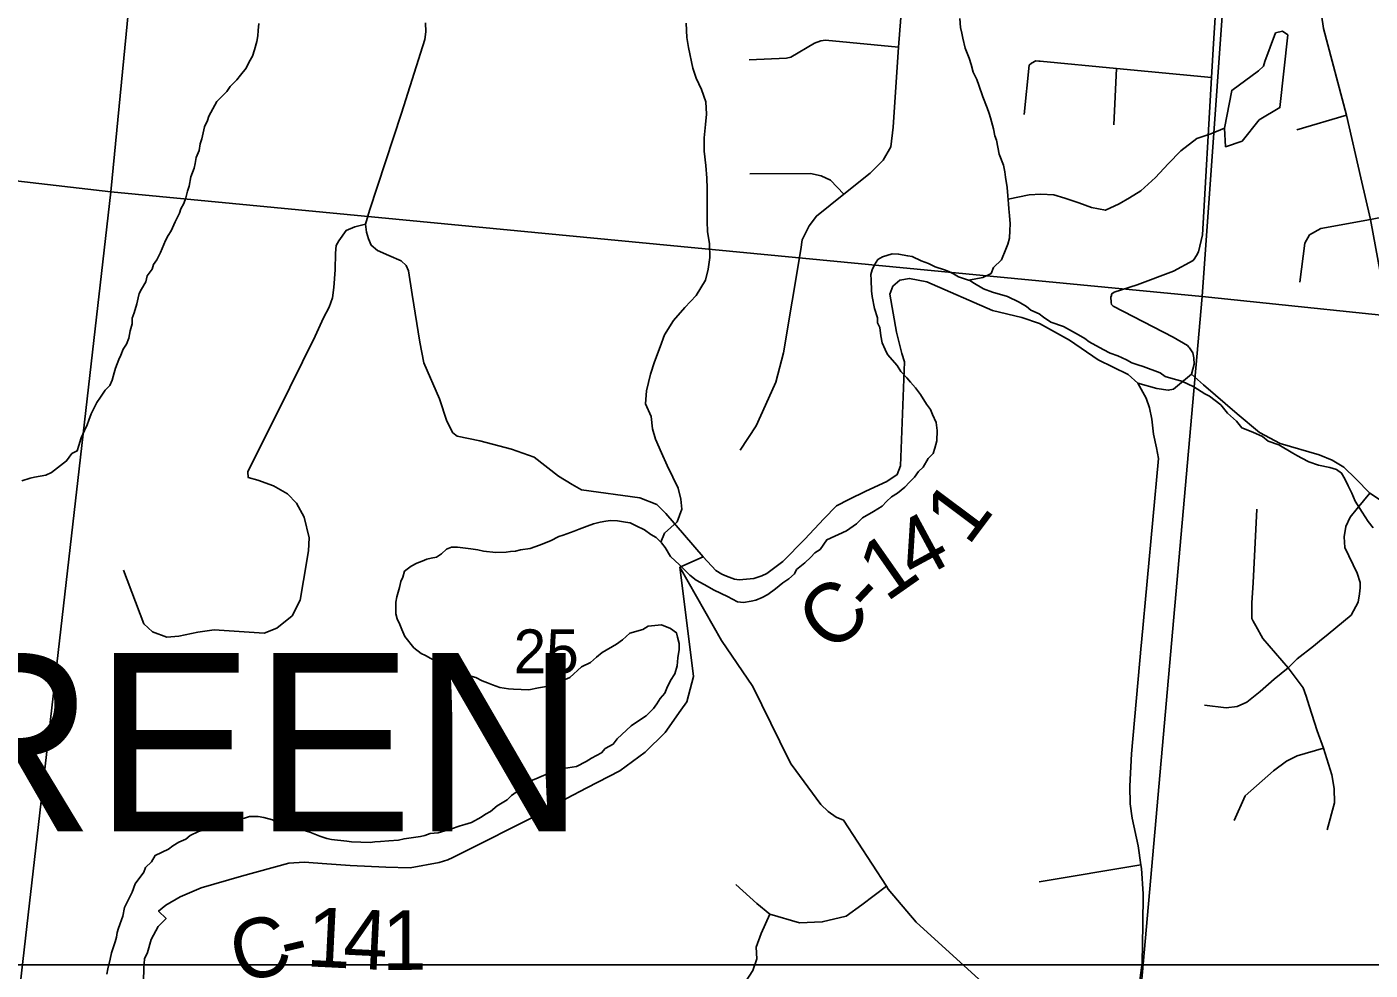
# Model space of a CAD drawing. Extents: x 0 to 34, y 0 to 22.
# Drawn here: x 4.767 to 6.05, y 17.836 to 18.737 of the extents above; entities that cross this region are included whole.
import ezdxf

# ---------------------------------------------------------------- set-up
doc = ezdxf.new("R2010")
doc.units = 0
for name, color, linetype in [('GM_X_Corporation', 7, 'Continuous'), ('GM_X_County_Road', 7, 'Continuous'), ('GM_X_County_Road_Text', 7, 'Continuous'), ('GM_X_Minor_Lake', 7, 'Continuous'), ('GM_X_Minor_River', 7, 'Continuous'), ('GM_X_Section_Text', 7, 'Continuous'), ('GM_X_Township_Road', 7, 'Continuous'), ('GM_X_Township_Text', 7, 'Continuous'), ('SH_Masking', 7, 'Continuous'), ('SH_Text', 7, 'Continuous')]:
    doc.layers.add(name, color=color, linetype=linetype)

msp = doc.modelspace()

# ---------------------------------------------------------------- linework, layer by layer
at = {"layer": 'GM_X_Corporation'}
for points in [[(3.9403, 19.7031), (4.9462, 19.5973), (4.8473, 18.5791), (3.8378, 18.696)], [(5.9616, 19.4927), (5.8893, 18.4792), (4.8473, 18.5791), (4.9462, 19.5973)], [(5.9616, 19.4927), (6.9413, 19.3834), (6.8431, 18.3799), (5.8893, 18.4792)], [(4.8473, 18.5791), (4.7377, 17.6243), (3.7435, 17.7155), (3.8378, 18.696)], [(4.8473, 18.5791), (5.8893, 18.4792), (5.7989, 17.4561), (4.7377, 17.6243)], [(6.8431, 18.3799), (6.7271, 17.3517), (5.7989, 17.4561), (5.8893, 18.4792)]]:
    msp.add_lwpolyline(points, close=True, dxfattribs=at)
at = {"layer": 'GM_X_County_Road'}
for p, q in [((5.3905, 18.2207), (5.4127, 18.2304)), ((5.3952, 18.1827), (5.3905, 18.2207))]:
    msp.add_line(p, q, dxfattribs=at)
for points in [[(5.8839, 18.5182), (5.8859, 18.5217), (5.8895, 18.5379), (5.8981, 18.6884), (5.9, 18.7207), (5.912, 18.9053), (5.9168, 18.9788)], [(5.4127, 18.2304), (5.3773, 18.2718), (5.3685, 18.2804), (5.3524, 18.287), (5.2965, 18.2945), (5.2876, 18.2997), (5.2746, 18.3077), (5.2513, 18.3256), (5.2299, 18.3335), (5.1995, 18.3413), (5.178, 18.3458), (5.1739, 18.349), (5.1682, 18.3602), (5.161, 18.3815), (5.1461, 18.4159), (5.1422, 18.4354), (5.1351, 18.481), (5.1316, 18.5038), (5.1292, 18.5088), (5.1246, 18.5132), (5.1128, 18.5184), (5.1017, 18.5232), (5.0957, 18.5281), (5.0934, 18.5341), (5.0914, 18.5407), (5.0903, 18.5483), (5.0941, 18.5614), (5.1249, 18.6542), (5.1472, 18.7247), (5.148, 18.7319), (5.1476, 18.7405)], [(5.8029, 18.4808), (5.8032, 18.4818), (5.8054, 18.4833), (5.8273, 18.4902), (5.8618, 18.5035), (5.8807, 18.5135), (5.8824, 18.5156), (5.8834, 18.5173), (5.8839, 18.5182)], [(5.4127, 18.2304), (5.4249, 18.2176), (5.4307, 18.2141), (5.435, 18.2121), (5.4428, 18.2092), (5.4473, 18.2086), (5.4613, 18.2098), (5.4688, 18.2124), (5.4736, 18.2147), (5.4888, 18.226), (5.5099, 18.2474), (5.528, 18.2669), (5.5402, 18.2791), (5.5518, 18.2852), (5.5683, 18.2934), (5.5883, 18.3026), (5.598, 18.3091), (5.6013, 18.3174), (5.605, 18.4168), (5.6026, 18.4248), (5.5975, 18.4451), (5.5912, 18.4814), (5.5941, 18.4889), (5.6007, 18.4948), (5.6098, 18.4964), (5.6264, 18.4932), (5.6892, 18.4657), (5.7171, 18.4591), (5.7339, 18.4533), (5.7626, 18.4375), (5.79, 18.4188), (5.8188, 18.4046), (5.828, 18.3963)], [(5.879, 18.4051), (5.8817, 18.4145), (5.8815, 18.4207), (5.8803, 18.4255), (5.8772, 18.43), (5.8767, 18.4307), (5.8752, 18.4323), (5.8616, 18.4404), (5.8042, 18.47), (5.8026, 18.4716), (5.8024, 18.4735), (5.8022, 18.4788), (5.8026, 18.4798), (5.8029, 18.4808)], [(5.828, 18.3963), (5.846, 18.3912), (5.857, 18.3897), (5.862, 18.3907), (5.879, 18.4051)], [(5.8315, 18.1487), (5.8476, 18.3243), (5.8457, 18.3346), (5.8427, 18.3476), (5.8413, 18.3621), (5.839, 18.3728), (5.8359, 18.382), (5.828, 18.3963)], [(5.879, 18.4051), (5.8905, 18.3947), (5.9226, 18.3671), (5.9442, 18.3494), (5.9637, 18.3388), (6.0009, 18.328), (6.0136, 18.3228), (6.0245, 18.3163), (6.036, 18.305), (6.0493, 18.2915), (6.0768, 18.2732), (6.0947, 18.2643), (6.1384, 18.2479), (6.1507, 18.2449), (6.1624, 18.2455), (6.1754, 18.2495), (6.1913, 18.2616), (6.2051, 18.2755), (6.2269, 18.3064), (6.2439, 18.3224), (6.2453, 18.3236), (6.2495, 18.3272)], [(5.4947, 18.0367), (5.4604, 18.1066), (5.4302, 18.1506), (5.3905, 18.2207)], [(5.3018, 18.0099), (5.3332, 18.0261), (5.3573, 18.0441), (5.3765, 18.0627), (5.3914, 18.084), (5.3971, 18.092), (5.4035, 18.1163), (5.3952, 18.1827)], [(5.7951, 17.4608), (5.8068, 17.5857), (5.8243, 17.786), (5.8319, 17.8427), (5.8327, 17.8792), (5.8329, 17.9088), (5.8314, 17.9328), (5.8309, 17.9365), (5.8283, 17.9545), (5.8224, 17.9809), (5.8205, 17.9946), (5.8203, 18.0114), (5.8217, 18.0425), (5.8312, 18.1458), (5.8315, 18.1487)], [(5.8243, 17.786), (5.734, 17.7824), (5.7265, 17.7846), (5.7175, 17.7898), (5.6762, 17.8273), (5.6163, 17.8816), (5.5896, 17.9132), (5.5878, 17.916), (5.5467, 17.9791), (5.5399, 17.982), (5.5322, 17.9872), (5.5252, 17.9939), (5.4969, 18.0324), (5.4947, 18.0367)], [(4.8763, 17.7392), (4.8786, 17.8378), (4.8794, 17.8465), (4.8821, 17.8527), (4.8858, 17.865), (4.8925, 17.8774), (4.8999, 17.8853), (4.8928, 17.8923), (4.8996, 17.8978), (4.9135, 17.9059), (4.9334, 17.9145), (4.9719, 17.9255), (5.0173, 17.9381), (5.0318, 17.9389), (5.0534, 17.9373), (5.0757, 17.9357), (5.1098, 17.9342), (5.1329, 17.9337), (5.1607, 17.9388), (5.1691, 17.9413), (5.1737, 17.9434), (5.2614, 17.9874), (5.2823, 17.9999), (5.3018, 18.0099)]]:
    msp.add_lwpolyline(points, dxfattribs=at)
at = {"layer": 'GM_X_Minor_Lake'}
for points in [[(5.9274, 18.6275), (5.9439, 18.648), (5.9636, 18.6596), (5.9711, 18.729), (5.9659, 18.7325), (5.9594, 18.7308), (5.9492, 18.7037), (5.9479, 18.6992), (5.9432, 18.6947), (5.9176, 18.676), (5.9106, 18.64)], [(5.9106, 18.64), (5.9117, 18.6222), (5.9274, 18.6275)]]:
    msp.add_lwpolyline(points, dxfattribs=at)
at = {"layer": 'GM_X_Minor_River'}
for points in [[(5.3725, 18.2447), (5.376, 18.253), (5.3881, 18.264), (5.3923, 18.2761), (5.3914, 18.2856), (5.389, 18.296), (5.384, 18.3067), (5.3783, 18.3179), (5.3729, 18.3299), (5.3672, 18.343), (5.3645, 18.3529), (5.3633, 18.3644), (5.3579, 18.3767), (5.3587, 18.3892), (5.3626, 18.4051), (5.3663, 18.4168), (5.3717, 18.431), (5.3758, 18.4427), (5.3846, 18.4562), (5.3952, 18.4688), (5.4061, 18.4802), (5.4149, 18.4948), (5.4175, 18.5054), (5.4193, 18.5164), (5.419, 18.5297), (5.417, 18.5408), (5.4165, 18.551), (5.4168, 18.5605), (5.4168, 18.572), (5.4167, 18.5822), (5.4162, 18.5921), (5.4154, 18.6043), (5.4139, 18.618), (5.4139, 18.6306), (5.415, 18.6435), (5.4161, 18.6533), (5.4153, 18.6651), (5.4111, 18.6767), (5.4061, 18.6875), (5.4029, 18.6971), (5.3989, 18.7169), (5.3973, 18.7265), (5.3966, 18.7402)], [(5.6667, 18.7067), (5.6629, 18.7163), (5.6609, 18.7259), (5.6599, 18.7305), (5.6586, 18.7359), (5.6578, 18.7447)], [(4.9765, 18.6972), (4.9794, 18.7031), (4.9826, 18.7087), (4.9843, 18.7148), (4.9865, 18.7227), (4.9875, 18.728), (4.988, 18.7333), (4.9886, 18.7397)], [(5.4586, 18.1882), (5.4632, 18.1892), (5.4693, 18.1917), (5.4747, 18.1945), (5.4818, 18.2), (5.4888, 18.2058), (5.4946, 18.2094), (5.5001, 18.2142), (5.5021, 18.2183), (5.51, 18.2248), (5.5158, 18.2303), (5.5194, 18.2344), (5.5244, 18.2376), (5.5308, 18.2469), (5.5497, 18.2554), (5.5591, 18.2619), (5.565, 18.2678), (5.5754, 18.2739), (5.5836, 18.2789), (5.5879, 18.2833), (5.5926, 18.2877), (5.5984, 18.2913), (5.6055, 18.2972), (5.6098, 18.302), (5.6145, 18.3067), (5.6185, 18.3119), (5.6228, 18.3163), (5.6277, 18.3245), (5.6324, 18.3293), (5.6341, 18.3342), (5.6359, 18.3414), (5.6362, 18.3512), (5.6353, 18.3589), (5.6318, 18.3666), (5.63, 18.3712), (5.626, 18.3763), (5.6203, 18.3856), (5.6156, 18.3919), (5.6108, 18.3973), (5.6072, 18.4016), (5.6017, 18.4075), (5.5981, 18.4134), (5.589, 18.4239), (5.5865, 18.4286), (5.5836, 18.4348), (5.5824, 18.4417), (5.5815, 18.4497), (5.5794, 18.4539), (5.5792, 18.4589), (5.5764, 18.4677), (5.5742, 18.4792), (5.5736, 18.4845), (5.5732, 18.4952), (5.573, 18.5001), (5.5743, 18.5047), (5.5764, 18.5095), (5.5796, 18.5144), (5.5842, 18.5169), (5.5934, 18.52), (5.5995, 18.5197), (5.6082, 18.5179), (5.6123, 18.5174), (5.6209, 18.5133), (5.628, 18.5108), (5.6344, 18.5075), (5.6434, 18.5045), (5.6475, 18.5029), (5.652, 18.5008), (5.6568, 18.498), (5.6662, 18.4946), (5.6716, 18.4956), (5.68, 18.4972), (5.6877, 18.5011), (5.6902, 18.5067), (5.6976, 18.5141), (5.7018, 18.5242), (5.7038, 18.5291), (5.7052, 18.5347), (5.7058, 18.5423), (5.706, 18.5487), (5.7055, 18.5564), (5.7046, 18.5629), (5.7044, 18.5678), (5.7039, 18.5754), (5.7031, 18.5831), (5.7015, 18.593), (5.7009, 18.5983), (5.6996, 18.6045), (5.6954, 18.6152), (5.6928, 18.6283), (5.6915, 18.6325), (5.6902, 18.6394), (5.6871, 18.6497), (5.6858, 18.654), (5.684, 18.6594), (5.6799, 18.6698), (5.6761, 18.6809), (5.674, 18.6863), (5.6708, 18.6933), (5.6688, 18.7006), (5.6667, 18.7067)], [(4.7621, 18.3032), (4.7701, 18.3056), (4.7743, 18.3066), (4.785, 18.3085), (4.7904, 18.311), (4.8049, 18.3222), (4.81, 18.3293), (4.8151, 18.3318), (4.8168, 18.337), (4.8189, 18.3442), (4.8222, 18.3513), (4.8247, 18.3565), (4.8263, 18.361), (4.8284, 18.367), (4.8337, 18.3779), (4.8373, 18.3831), (4.8418, 18.3898), (4.8461, 18.3942), (4.8485, 18.3994), (4.8503, 18.4062), (4.8516, 18.4107), (4.8549, 18.419), (4.8569, 18.4231), (4.859, 18.4287), (4.8622, 18.4335), (4.8644, 18.4395), (4.8657, 18.4463), (4.8675, 18.4531), (4.8677, 18.4584), (4.8694, 18.4637), (4.8719, 18.472), (4.8733, 18.478), (4.8742, 18.4821), (4.8766, 18.4862), (4.8806, 18.4933), (4.882, 18.499), (4.8867, 18.5053), (4.888, 18.5098), (4.8912, 18.5142), (4.8945, 18.5213), (4.8995, 18.5326), (4.9019, 18.5374), (4.9047, 18.5419), (4.9088, 18.5505), (4.9129, 18.5587), (4.9142, 18.5629), (4.917, 18.5681), (4.9187, 18.5733), (4.9205, 18.5797), (4.9221, 18.5846), (4.9236, 18.5933), (4.9269, 18.6016), (4.9278, 18.6061), (4.9288, 18.6118), (4.9317, 18.6185), (4.9326, 18.6249), (4.934, 18.6298), (4.9366, 18.6411), (4.9395, 18.6471), (4.9408, 18.6513), (4.9485, 18.6654), (4.9579, 18.675), (4.9611, 18.6798), (4.9674, 18.6861), (4.971, 18.6905), (4.9765, 18.6972)], [(5.7041, 18.572), (5.7241, 18.5761), (5.7352, 18.5769), (5.7477, 18.5762), (5.7582, 18.5732), (5.7714, 18.5687), (5.7838, 18.5641), (5.797, 18.5615), (5.8101, 18.5676), (5.8198, 18.5734), (5.8306, 18.5799), (5.8447, 18.5928), (5.8568, 18.6058), (5.8689, 18.6183), (5.8841, 18.6301), (5.8975, 18.6346), (5.9106, 18.64)], [(5.667, 18.4948), (5.6703, 18.4926), (5.6804, 18.4865), (5.689, 18.4832), (5.7033, 18.4793), (5.7145, 18.4736), (5.7215, 18.4695), (5.7256, 18.466), (5.7338, 18.4626), (5.7379, 18.4595), (5.7449, 18.4546), (5.7569, 18.4504), (5.7711, 18.4427), (5.7774, 18.4391), (5.7815, 18.4359), (5.7949, 18.4286), (5.8016, 18.4249), (5.8087, 18.4224), (5.817, 18.4187), (5.8222, 18.4159), (5.8278, 18.4138), (5.8331, 18.4124), (5.8492, 18.4062), (5.854, 18.4026), (5.8638, 18.4), (5.8698, 18.3983), (5.8814, 18.3929), (5.8918, 18.3861), (5.8963, 18.384), (5.907, 18.3757), (5.9135, 18.3678), (5.922, 18.36), (5.9271, 18.3537), (5.9376, 18.3495), (5.9469, 18.3454), (5.9525, 18.341), (5.9626, 18.3376), (5.976, 18.3296), (5.9805, 18.3271), (5.9846, 18.3247), (5.9913, 18.3214), (6.0003, 18.3181), (6.0112, 18.3158), (6.0176, 18.3141), (6.0224, 18.3105), (6.0257, 18.305), (6.0288, 18.2985), (6.0324, 18.2915), (6.0355, 18.2838), (6.042, 18.2733), (6.0478, 18.2644), (6.0525, 18.2581)], [(5.3815, 18.1126), (5.3859, 18.1189), (5.3881, 18.1264), (5.3887, 18.134), (5.3898, 18.142), (5.39, 18.1477), (5.3883, 18.1538), (5.3873, 18.158), (5.3817, 18.162), (5.3731, 18.1657), (5.3602, 18.1643), (5.3551, 18.161), (5.3429, 18.1576), (5.3358, 18.1514), (5.33, 18.1471), (5.3164, 18.1392), (5.3109, 18.1348), (5.3051, 18.1297), (5.2966, 18.1254), (5.2856, 18.1152), (5.2721, 18.1095), (5.2671, 18.1074), (5.2556, 18.1056), (5.2465, 18.1036), (5.2317, 18.1041), (5.2271, 18.1046), (5.2188, 18.1057), (5.2117, 18.1082), (5.2068, 18.1103), (5.2019, 18.112), (5.1956, 18.1152), (5.1866, 18.1178), (5.1783, 18.1212), (5.1731, 18.124), (5.1656, 18.1265), (5.1615, 18.129), (5.1529, 18.1334), (5.1477, 18.1363), (5.1436, 18.1383), (5.1366, 18.1435), (5.1279, 18.1545), (5.125, 18.161), (5.1233, 18.166), (5.1205, 18.1714), (5.1195, 18.176), (5.1193, 18.181), (5.1195, 18.1874), (5.1204, 18.1923), (5.123, 18.2014), (5.124, 18.207), (5.126, 18.2111), (5.1277, 18.2168), (5.134, 18.2215), (5.1394, 18.2244), (5.1444, 18.2265), (5.149, 18.2282), (5.1532, 18.2292), (5.1582, 18.2302), (5.1629, 18.2334), (5.1676, 18.2378), (5.1726, 18.2399), (5.1783, 18.2397), (5.1911, 18.2382), (5.1975, 18.2372), (5.2032, 18.2358), (5.2149, 18.2347), (5.2248, 18.2351), (5.229, 18.2357), (5.2336, 18.2359), (5.2385, 18.2373), (5.2477, 18.2385), (5.2565, 18.2416), (5.2669, 18.2458), (5.2751, 18.2501), (5.2793, 18.2511), (5.2896, 18.2549), (5.2943, 18.257), (5.302, 18.2598), (5.3081, 18.2619), (5.3146, 18.2635), (5.32, 18.2645), (5.3245, 18.2651), (5.331, 18.2649), (5.3386, 18.2638), (5.3431, 18.2629), (5.3487, 18.2601), (5.3569, 18.2564), (5.3628, 18.252), (5.368, 18.2491), (5.3732, 18.244), (5.3764, 18.2393), (5.3815, 18.2308), (5.3903, 18.2229), (5.4002, 18.2131), (5.4061, 18.2083), (5.4139, 18.2042), (5.4232, 18.1986), (5.436, 18.1928), (5.4456, 18.1875), (5.4513, 18.187), (5.4586, 18.1882)], [(4.8434, 17.8321), (4.8443, 17.837), (4.8465, 17.8464), (4.8479, 17.8524), (4.8513, 17.863), (4.8526, 17.8675), (4.8531, 17.8717), (4.8544, 17.8758), (4.8586, 17.8874), (4.8604, 17.8957), (4.8677, 17.9103), (4.8703, 17.9182), (4.8786, 17.9293), (4.8803, 17.9338), (4.8862, 17.9393), (4.8894, 17.9453), (4.9022, 17.9513), (4.9064, 17.9546), (4.9123, 17.9582), (4.9188, 17.961), (4.9231, 17.9643), (4.9308, 17.9682), (4.9427, 17.9716), (4.9482, 17.9756), (4.9562, 17.9776), (4.9749, 17.9811), (4.9795, 17.9825), (4.9879, 17.9825), (4.9932, 17.9816), (5.0015, 17.9794), (5.0055, 17.977), (5.0191, 17.9739), (5.0232, 17.9722), (5.0285, 17.9701), (5.0371, 17.9675), (5.0469, 17.9638), (5.0536, 17.9616), (5.0578, 17.9607), (5.0725, 17.9591), (5.077, 17.9585), (5.0949, 17.9579), (5.0994, 17.9585), (5.1048, 17.9587), (5.1128, 17.9592), (5.1219, 17.96), (5.1273, 17.9614), (5.1318, 17.962), (5.1429, 17.9635), (5.1471, 17.9645), (5.1521, 17.9662), (5.1597, 17.9671), (5.1716, 17.9705), (5.1808, 17.9736), (5.1851, 17.975), (5.1916, 17.977), (5.2009, 17.982), (5.2051, 17.9849), (5.2098, 17.9874), (5.2161, 17.9929), (5.2257, 17.9986), (5.2297, 18.0027), (5.2375, 18.0081), (5.2411, 18.0137), (5.2457, 18.0158), (5.253, 18.0186), (5.258, 18.0207), (5.2642, 18.0232), (5.2745, 18.0255), (5.2795, 18.0283), (5.2918, 18.0302), (5.301, 18.0352), (5.3061, 18.0384), (5.3158, 18.0434), (5.3193, 18.0475), (5.327, 18.0518), (5.3306, 18.0566), (5.344, 18.069), (5.3529, 18.0752), (5.3584, 18.0788), (5.3654, 18.0858), (5.3686, 18.0902), (5.3718, 18.0954), (5.3762, 18.1002), (5.3782, 18.1051), (5.3815, 18.1126)]]:
    msp.add_lwpolyline(points, dxfattribs=at)
at = {"layer": 'GM_X_Township_Road'}
for p, q in [((5.805, 18.6432), (5.8075, 18.697)), ((5.9796, 18.6383), (6.0271, 18.6522)), ((5.7336, 17.9203), (5.8309, 17.9365))]:
    msp.add_line(p, q, dxfattribs=at)
for points in [[(5.4483, 18.3325), (5.4635, 18.3557), (5.4725, 18.3755), (5.4821, 18.3974), (5.4894, 18.4252), (5.5061, 18.5239), (5.5075, 18.5334), (5.5139, 18.5465), (5.521, 18.556), (5.547, 18.5769), (5.5722, 18.5968), (5.5847, 18.6094), (5.5919, 18.6221), (5.5943, 18.6408), (5.5995, 18.7171), (5.6067, 18.8106)], [(5.9971, 18.7897), (5.9988, 18.7743), (6.0016, 18.7591), (6.0053, 18.735), (6.0271, 18.6522), (6.0409, 18.5926)], [(5.5995, 18.7171), (5.5297, 18.7238), (5.5251, 18.7232), (5.519, 18.7212), (5.4966, 18.7078), (5.4924, 18.7068), (5.4567, 18.7053)], [(5.7192, 18.6528), (5.7242, 18.7001), (5.7265, 18.7019), (5.7304, 18.7041), (5.7335, 18.704), (5.7345, 18.704), (5.8075, 18.697), (5.8981, 18.6884)], [(5.4573, 18.5963), (5.5154, 18.5966), (5.5255, 18.5945), (5.5343, 18.5904), (5.547, 18.5769)], [(6.0409, 18.5926), (6.0501, 18.5528), (6.0618, 18.4887), (6.0696, 18.4687), (6.0813, 18.4569), (6.1116, 18.4212), (6.1537, 18.3796)], [(5.9825, 18.4927), (5.9874, 18.53), (5.9918, 18.5379), (6.0025, 18.5441), (6.0501, 18.5528), (6.0908, 18.5605), (6.1019, 18.5607), (6.1118, 18.5585), (6.1221, 18.5506), (6.1398, 18.5276)], [(4.8593, 18.2179), (4.8787, 18.1667), (4.8871, 18.159), (4.9006, 18.1537), (4.9121, 18.1547), (4.9304, 18.1585), (4.946, 18.1608), (4.9937, 18.1575), (5.0057, 18.1623), (5.0205, 18.1743), (5.0281, 18.1891), (5.0312, 18.208), (5.036, 18.2363), (5.0365, 18.2486), (5.0317, 18.2684), (5.0246, 18.2817), (5.0159, 18.2906), (5.0024, 18.2983), (4.9876, 18.3039), (4.9784, 18.3062), (4.9779, 18.3118), (5.018, 18.3921), (5.0422, 18.4413), (5.0504, 18.4588), (5.0556, 18.4691), (5.0588, 18.4779), (5.06, 18.4879), (5.0615, 18.5047), (5.0617, 18.5206), (5.0623, 18.5277), (5.0648, 18.5323), (5.0719, 18.5421), (5.0802, 18.5458), (5.0903, 18.5483)], [(6.0493, 18.2915), (6.0373, 18.2767), (6.0308, 18.2684), (6.0266, 18.2595), (6.0248, 18.2497), (6.0256, 18.2396), (6.0373, 18.2148), (6.0401, 18.2061), (6.0402, 18.2009), (6.0397, 18.1952), (6.0384, 18.1871), (6.0315, 18.1748), (6.0096, 18.1568), (6.0015, 18.1501)], [(5.9416, 18.276), (5.938, 18.2058), (5.9368, 18.1867), (5.9367, 18.1717), (5.938, 18.1692), (5.9405, 18.1648)], [(5.9405, 18.1648), (5.9474, 18.1524), (5.9716, 18.1244), (5.9859, 18.1054), (5.9887, 18.0975), (5.9916, 18.0882)], [(6.0015, 18.1501), (5.9956, 18.1453), (5.9802, 18.133), (5.9716, 18.1244), (5.9581, 18.1137), (5.9446, 18.102), (5.9321, 18.0919), (5.9226, 18.0876), (5.9122, 18.0862), (5.8915, 18.0889)], [(5.9916, 18.0882), (5.9992, 18.0645), (6.0053, 18.0479), (6.0132, 18.0224), (6.0153, 18.0093), (6.0156, 17.9955), (6.0087, 17.9699)], [(5.92, 17.9787), (5.9305, 18.0022), (5.9573, 18.0262), (5.97, 18.0355), (5.9799, 18.0405), (6.0053, 18.0479)], [(5.444, 17.9175), (5.464, 17.8995), (5.4764, 17.8892), (5.5047, 17.8809), (5.5265, 17.8819), (5.5493, 17.8874), (5.5645, 17.8981), (5.5878, 17.916)], [(5.4288, 17.7956), (5.4367, 17.8056), (5.4443, 17.8149), (5.4533, 17.8246), (5.4603, 17.8356), (5.464, 17.8467), (5.4633, 17.8577), (5.4682, 17.8709), (5.4764, 17.8892)]]:
    msp.add_lwpolyline(points, dxfattribs=at)
at = {"layer": 'SH_Masking'}
msp.add_lwpolyline([(4.6164, 17.841), (6.3738, 17.841), (6.3738, 17.3215), (4.6164, 17.3215)], close=True, dxfattribs=at)
at = {"layer": 'SH_Text'}
msp.add_lwpolyline([(4.6164, 17.841), (6.3738, 17.841), (6.3738, 17.3215), (4.6164, 17.3215)], close=True, dxfattribs=at)

# ---------------------------------------------------------------- texts
at = {"layer": 'GM_X_County_Road_Text'}
for s, rotation, p in [('1', 53.1852, (5.6659, 18.24)), ('4', 28.3725, (5.6149, 18.2059)), ('1', 34.9552, (5.5877, 18.1868)), ('C', 41.3144, (5.5348, 18.137)), ('-', 46.584, (5.574, 18.1718)), ('1', 357.1679, (5.0333, 17.8396)), ('C', 15.2447, (4.9703, 17.8225)), ('4', 357.1575, (5.0683, 17.8379)), ('1', 0.1017, (5.1064, 17.8361)), ('-', 13.4238, (5.0149, 17.8346))]:
    msp.add_text(s, height=0.0568, rotation=rotation, dxfattribs=at).set_placement(p)
at = {"layer": 'GM_X_Section_Text'}
msp.add_text('25', height=0.04186, rotation=0, dxfattribs=at).set_placement((5.2318, 18.1194))
at = {"layer": 'GM_X_Township_Text'}
msp.add_text('GREEN', height=0.17045, rotation=0, dxfattribs=at).set_placement((4.4896, 17.9684))

doc.saveas('drawing.dxf')
